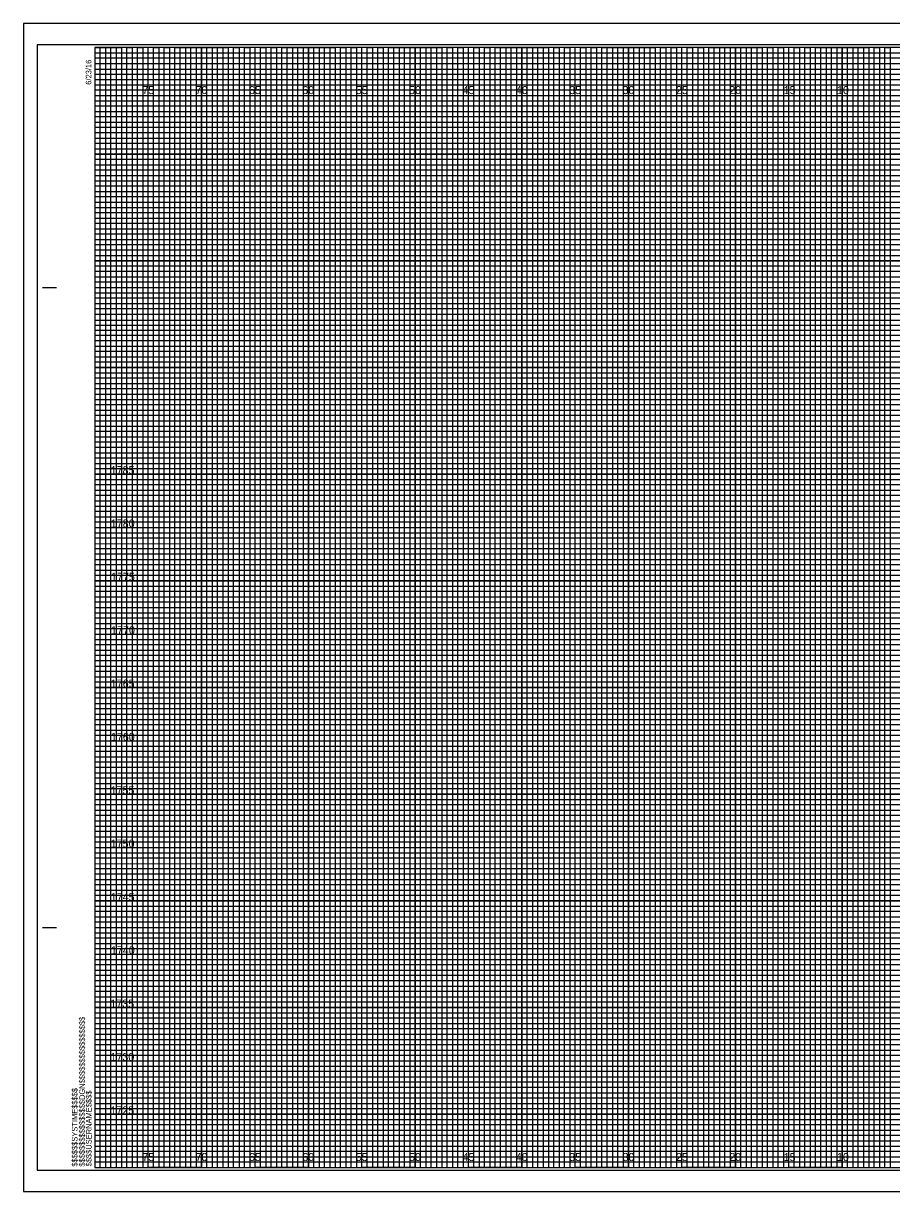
# Model space of a CAD drawing. Extents: x -7 to 162, y -2 to 437.
# Drawn here: x -6.7 to 74.6, y 107.7 to 217.2 of the extents above; entities that cross this region are included whole.
import ezdxf

# ---------------------------------------------------------------- set-up
doc = ezdxf.new("R2010")
doc.units = 0
for name, color, linetype in [('Raster_Level_0', 7, 'Continuous'), ('Scratch_Level_3', 7, 'Continuous'), ('Sheet Cross Section CELL', 7, 'Continuous'), ('Sheet Cross Section Grid Major CELL', 7, 'Continuous'), ('Sheet Cross Section Grid Middle CELL', 7, 'Continuous'), ('Sheet Cross Section Grid Minor 1 CELL', 7, 'Continuous'), ('Sheet Cross Section Grid Minor 2 CELL', 7, 'Continuous'), ('Sheet Cutting Line CELL', 7, 'Continuous'), ('Sheet DOT Grid CELL', 7, 'Continuous'), ('Sheet Plot Border Inside CELL', 7, 'Continuous'), ('Sheet Plot Border Outside CELL', 7, 'Continuous')]:
    doc.layers.add(name, color=color, linetype=linetype)

msp = doc.modelspace()

# ---------------------------------------------------------------- linework, layer by layer
at = {"layer": 'Sheet Cross Section CELL'}
for p, q in [((-4.9, 192.5), (-3.65, 192.5)), ((-4.85, 192.5), (-3.6, 192.5)), ((-4.9, 132.5), (-3.65, 132.5)), ((-4.85, 132.5), (-3.6, 132.5)), ((0, 110), (0, 110)), ((0, 110), (0, 110)), ((0, 110), (0, 110)), ((0, 110), (0, 110)), ((0, 110), (0, 110)), ((0, 110), (0, 110)), ((0, 110), (0, 110))]:
    msp.add_line(p, q, dxfattribs=at)
msp.add_lwpolyline([(160, 215), (0, 215), (0, 110), (160, 110)], close=True, dxfattribs=at)
at = {"layer": 'Sheet Cross Section Grid Major CELL'}
for p, q in [((5, 215), (0, 215)), ((5, 110), (5, 215)), ((15, 215), (10, 215)), ((10, 215), (10, 110)), ((15, 110), (15, 215)), ((25, 215), (20, 215)), ((20, 215), (20, 110)), ((25, 110), (25, 215)), ((35, 215), (30, 215)), ((30, 215), (30, 110)), ((35, 110), (35, 215)), ((45, 215), (40, 215)), ((40, 215), (40, 110)), ((45, 110), (45, 215)), ((55, 215), (50, 215)), ((50, 215), (50, 110)), ((55, 110), (55, 215)), ((65, 215), (60, 215)), ((60, 215), (60, 110)), ((65, 110), (65, 215)), ((75, 215), (70, 215)), ((70, 215), (70, 110)), ((10, 110), (5, 110)), ((20, 110), (15, 110)), ((30, 110), (25, 110)), ((40, 110), (35, 110)), ((50, 110), (45, 110)), ((60, 110), (55, 110)), ((70, 110), (65, 110))]:
    msp.add_line(p, q, dxfattribs=at)
for points in [[(0, 210), (160, 210), (160, 205), (0, 205)], [(0, 200), (160, 200), (160, 195), (0, 195)], [(0, 190), (160, 190), (160, 185), (0, 185)], [(0, 180), (160, 180), (160, 175), (0, 175)], [(0, 170), (160, 170), (160, 165), (0, 165)], [(0, 160), (160, 160), (160, 155), (0, 155)], [(0, 150), (160, 150), (160, 145), (0, 145)], [(0, 140), (160, 140), (160, 135), (0, 135)], [(0, 130), (160, 130), (160, 125), (0, 125)], [(0, 120), (160, 120), (160, 115), (0, 115)]]:
    msp.add_lwpolyline(points, dxfattribs=at)
at = {"layer": 'Sheet Cross Section Grid Middle CELL'}
for points in [[(0, 215), (2.5, 215), (2.5, 110), (7.5, 110), (7.5, 215), (12.5, 215), (12.5, 110), (17.5, 110), (17.5, 215), (22.5, 215), (22.5, 110), (27.5, 110), (27.5, 215), (32.5, 215), (32.5, 110), (37.5, 110), (37.5, 215), (42.5, 215), (42.5, 110), (47.5, 110), (47.5, 215), (52.5, 215), (52.5, 110), (57.5, 110), (57.5, 215), (62.5, 215), (62.5, 110), (67.5, 110), (67.5, 215), (72.5, 215), (72.5, 110), (77.5, 110)], [(0, 212.5), (137.5, 212.5)], [(0, 202.5), (160, 202.5), (160, 207.5), (0, 207.5)], [(0, 192.5), (160, 192.5), (160, 197.5), (0, 197.5)], [(0, 182.5), (160, 182.5), (160, 187.5), (0, 187.5)], [(0, 172.5), (160, 172.5), (160, 177.5), (0, 177.5)], [(0, 162.5), (160, 162.5), (160, 167.5), (0, 167.5)], [(0, 152.5), (160, 152.5), (160, 157.5), (0, 157.5)], [(0, 142.5), (160, 142.5), (160, 147.5), (0, 147.5)], [(0, 132.5), (160, 132.5), (160, 137.5), (0, 137.5)], [(0, 122.5), (160, 122.5), (160, 127.5), (0, 127.5)], [(0, 112.5), (160, 112.5), (160, 117.5), (0, 117.5)]]:
    msp.add_lwpolyline(points, dxfattribs=at)
at = {"layer": 'Sheet Cross Section Grid Minor 1 CELL'}
for p, q in [((0, 214.5), (130, 214.5)), ((130, 213.99), (0, 213.99)), ((0, 213.99), (0, 213.5)), ((0, 213.5), (130, 213.5)), ((130, 212.94), (0, 212.94)), ((0, 212.94), (0, 212)), ((0, 212), (160, 212))]:
    msp.add_line(p, q, dxfattribs=at)
for points in [[(0, 211.5), (135, 211.5), (160, 211.5), (160, 211), (0, 211)], [(0, 210.5), (160, 210.5), (160, 209.5), (0, 209.5)], [(0, 209), (160, 209), (160, 208.5), (0, 208.49)], [(0, 208), (160, 208), (160, 207), (0, 207)], [(0, 206.5), (160, 206.5), (160, 206), (0, 206)], [(0, 205.5), (160, 205.5), (160, 204.5), (0, 204.5)], [(0, 204), (160, 204), (160, 203.5), (0, 203.5)], [(0, 203), (160, 203), (160, 202), (0, 202)], [(0, 201.5), (160, 201.5), (160, 201), (0, 201)], [(0, 200.5), (160, 200.5), (160, 199.5), (0, 199.5)], [(0, 199), (160, 199), (160, 198.5), (0, 198.5)], [(0, 198), (160, 198), (160, 196.97), (160, 196.5), (160, 196), (0, 196)], [(0, 197), (160, 197), (160, 196.5), (0, 196.5)], [(0, 195.5), (160, 195.5), (160, 194.5), (0, 194.52)], [(0, 194.52), (160, 194.5), (160, 194), (0, 194)], [(0, 193.5), (160, 193.5), (160, 193), (0, 193)], [(0, 192), (160, 192), (160, 191.5), (0, 191.5)], [(0, 191), (160, 191), (160, 190.5), (0, 190.5)], [(-0.04, 189.44), (160, 189.44), (160, 188.94), (-0.04, 188.94)], [(0, 188.5), (160, 188.5), (160, 188), (0, 188)], [(0, 187), (160, 187), (160, 186.5), (0, 186.5)], [(0, 186), (160, 186), (160, 185.5), (0, 185.5)], [(0, 184.5), (160, 184.5), (160, 184), (0, 184)], [(0, 183.5), (160, 183.5), (160, 183), (0, 183)], [(0, 182), (160, 182), (160, 181.5), (0, 181.5)], [(0, 181), (160, 181), (160, 180.5), (0, 180.5)], [(0, 179.5), (160, 179.5), (160, 178.99), (0, 179)], [(0, 178.5), (160, 178.5), (160, 178), (0, 178)], [(0, 177), (160, 177), (160, 176.5), (0, 176.5)], [(0, 176), (160, 176), (160, 175.5), (0, 175.5)], [(0, 174.5), (160, 174.5), (160, 174), (0, 174)], [(0, 173.5), (160, 173.5), (160, 173), (0, 173)], [(0, 172), (160, 172), (160, 171.5), (0, 171.5)], [(0, 171), (160, 171), (160, 170.5), (0, 170.5)], [(0, 169.5), (160, 169.5), (160, 169), (0, 169)], [(0, 168.5), (160.03, 168.46), (160, 168), (0, 168)], [(0, 167), (160, 167), (160, 166.5), (0, 166.5)], [(0, 166), (160, 166), (160, 165.5), (0, 165.5)], [(0, 164.5), (160, 164.5), (160, 164), (0, 164)], [(0, 163.5), (160, 163.5), (160, 163), (0, 163)], [(0, 162), (160, 162), (160, 161.5), (0, 161.5)], [(0, 161), (160, 161), (160, 160.5), (0, 160.5)], [(0, 159.5), (160, 159.5), (160, 159), (0, 159)], [(0, 158.5), (160, 158.5), (160, 158), (0, 158)], [(0, 157), (160, 157), (160, 156.5), (0, 156.5)], [(0, 156), (160, 156), (160, 155.5), (0, 155.5)], [(0, 154.5), (160, 154.5), (160, 154), (0, 154)], [(0, 153.5), (160, 153.5), (160, 153), (0, 153)], [(0, 152), (160, 152), (160, 151.5), (0, 151.5)], [(0, 151), (160, 151), (160, 150.5), (0, 150.5)], [(0, 149.5), (160, 149.5), (160, 148.99), (0, 149)], [(0, 148.5), (160, 148.5), (160, 148), (0, 148)], [(0, 147), (160, 147), (160, 146.5), (0, 146.5)], [(0, 146), (160, 146), (160, 145.5), (0, 145.5)], [(0, 144.5), (160, 144.5), (160, 144), (0, 144)], [(0, 143.5), (160, 143.5), (160, 143), (0, 143)], [(0, 142), (160, 142), (160, 141.5), (0, 141.5)], [(0, 141), (160, 141), (160, 140.5), (0, 140.5)], [(0, 139.5), (160, 139.5), (160, 139), (0, 139)], [(0, 138.5), (160.03, 138.46), (160, 138), (0, 138)], [(0, 137), (160, 137), (160, 136.5), (0, 136.5)], [(0, 136), (160, 136), (160, 135.5), (0, 135.5)], [(0, 134.5), (160, 134.5), (160, 134), (0, 134)], [(0, 133.5), (160, 133.5), (160, 133), (0, 133)], [(0, 132), (160, 132), (160, 131.5), (0, 131.5)], [(0, 131), (160, 131), (160, 130.5), (0, 130.5)], [(0, 129.5), (160, 129.5), (160, 129), (0, 129)], [(0, 128.5), (160, 128.5), (160, 128), (0, 128)], [(0, 127), (160, 127), (160, 126.5), (0, 126.5)], [(0, 126), (160, 126), (160, 125.5), (0, 125.5)], [(0, 124.5), (160, 124.5), (160, 124), (0, 124)], [(0, 123.5), (160, 123.5), (160, 123), (0, 123)], [(0, 122), (160, 122), (160, 121.5), (0, 121.5)], [(0, 121), (160, 121), (160, 120.5), (0, 120.5)], [(0, 119.5), (160, 119.5), (160, 119), (0, 119)], [(0, 118.5), (160, 118.5), (160, 118), (0, 118)], [(0, 117), (160, 117), (160, 116.5), (0, 116.5)], [(0, 116), (160, 116), (160, 115.5), (0, 115.5)], [(0, 114.5), (160, 114.5), (160, 114), (0, 114)], [(0, 113.5), (160, 113.5), (160, 113), (0, 113)], [(0, 112), (160, 112), (160, 111.5), (0, 111.5)], [(0, 111), (160, 111), (160, 110.5), (0, 110.5)]]:
    msp.add_lwpolyline(points, dxfattribs=at)
at = {"layer": 'Sheet Cross Section Grid Minor 2 CELL'}
for points in [[(0, 110), (0.5, 110), (0.5, 215), (1, 215), (1, 110)], [(1, 110), (1.5, 110), (1.5, 215), (2, 215), (2, 110)], [(2.5, 110), (3, 110), (3, 215), (3.5, 215), (3.5, 110)], [(3.5, 110), (4, 110), (4, 215), (4.5, 215), (4.5, 110)], [(5, 110), (5.5, 110), (5.5, 215), (6, 215), (6, 110)], [(6, 110), (6.5, 110), (6.5, 215), (7, 215), (7, 110)], [(7.5, 110), (8, 110), (8, 215), (8.5, 215), (8.5, 110)], [(8.5, 110), (9, 110), (9, 215), (9.5, 215), (9.5, 110)], [(10, 110), (10.5, 110), (10.5, 215), (11, 215), (11, 110)], [(11, 110), (11.5, 110), (11.5, 215), (12, 215), (12, 110)], [(12.5, 110), (13, 110), (13, 215), (13.5, 215), (13.5, 110)], [(13.5, 110), (14, 110), (14, 215), (14.5, 215), (14.5, 110)], [(15, 110), (15.5, 110), (15.5, 215), (16, 215), (16, 110)], [(16, 110), (16.5, 110), (16.5, 215), (17, 215), (17, 110)], [(17.5, 110), (18, 110), (18, 215), (18.5, 215), (18.5, 110)], [(18.5, 110), (19, 110), (19, 215), (19.5, 215), (19.5, 110)], [(20, 110), (20.5, 110), (20.5, 215), (21, 215), (21, 110)], [(21, 110), (21.5, 110), (21.5, 215), (22, 215), (22, 110)], [(22.5, 110), (23, 110), (23, 215), (23.5, 215), (23.5, 110)], [(23.5, 110), (24, 110), (24, 215), (24.5, 215), (24.5, 110)], [(25, 110), (25.5, 110), (25.5, 215), (26, 215), (26, 110)], [(26, 110), (26.5, 110), (26.5, 215), (27, 215), (27, 110)], [(27.5, 110), (28, 110), (28, 215), (28.5, 215), (28.5, 110)], [(28.5, 110), (29, 110), (29, 215), (29.5, 215), (29.5, 110)], [(30, 110), (30.5, 110), (30.5, 215), (31, 215), (31, 110)], [(31, 110), (31.5, 110), (31.5, 215), (32, 215), (32, 110)], [(32.5, 110), (33, 110), (33, 215), (33.5, 215), (33.5, 110)], [(33.5, 110), (34, 110), (34, 215), (34.5, 215), (34.5, 110)], [(35, 110), (35.5, 110), (35.5, 215), (36, 215), (36, 110)], [(36, 110), (36.5, 110), (36.5, 215), (37, 215), (37, 110)], [(37.5, 110), (38, 110), (38, 215), (38.5, 215), (38.5, 110)], [(38.5, 110), (39, 110), (39, 215), (39.5, 215), (39.5, 110)], [(40, 110), (40.5, 110), (40.5, 215), (41, 215), (41, 110)], [(41, 110), (41.5, 110), (41.5, 215), (42, 215), (42, 110)], [(42.5, 110), (43, 110), (43, 215), (43.5, 215), (43.5, 110)], [(43.5, 110), (44, 110), (44, 215), (44.5, 215), (44.5, 110)], [(45, 110), (45.5, 110), (45.5, 215), (46, 215), (46, 110)], [(46, 110), (46.5, 110), (46.5, 215), (47, 215), (47, 110)], [(47.5, 110), (48, 110), (48, 215), (48.5, 215), (48.5, 110)], [(48.5, 110), (49, 110), (49, 215), (49.5, 215), (49.5, 110)], [(50, 110), (50.5, 110), (50.5, 215), (51, 215), (51, 110)], [(51, 110), (51.5, 110), (51.5, 215), (52, 215), (52, 110)], [(52.5, 110), (53, 110), (53, 215), (53.5, 215), (53.5, 110)], [(53.5, 110), (54, 110), (54, 215), (54.5, 215), (54.5, 110)], [(55, 110), (55.5, 110), (55.5, 215), (56, 215), (56, 110)], [(56, 110), (56.5, 110), (56.5, 215), (57, 215), (57, 110)], [(57.5, 110), (58, 110), (58, 215), (58.5, 215), (58.5, 110)], [(58.5, 110), (59, 110), (59, 215), (59.5, 215), (59.5, 110)], [(60, 110), (60.5, 110), (60.5, 215), (61, 215), (61, 110)], [(61, 110), (61.5, 110), (61.5, 215), (62, 215), (62, 110)], [(62.5, 110), (63, 110), (63, 215), (63.5, 215), (63.5, 110)], [(63.5, 110), (64, 110), (64, 215), (64.5, 215), (64.5, 110)], [(65, 110), (65.5, 110), (65.5, 215), (66, 215), (66, 110)], [(66, 110), (66.5, 110), (66.5, 215), (67, 215), (67, 110)], [(67.5, 110), (68, 110), (68, 215), (68.5, 215), (68.5, 110)], [(68.5, 110), (69, 110), (69, 215), (69.5, 215), (69.5, 110)], [(70, 110), (70.5, 110), (70.5, 215), (71, 215), (71, 110)], [(71, 110), (71.5, 110), (71.5, 215), (72, 215), (72, 110)], [(72.5, 110), (73, 110), (73, 215), (73.5, 215), (73.5, 110)], [(73.5, 110), (74, 110), (74, 215), (74.5, 215), (74.5, 110)]]:
    msp.add_lwpolyline(points, dxfattribs=at)
at = {"layer": 'Sheet Cutting Line CELL'}
for p, q in [((161.65, 217.25), (-6.7, 217.25)), ((-6.7, 217.25), (-6.7, 107.75)), ((-6.7, 107.75), (161.65, 107.75))]:
    msp.add_line(p, q, dxfattribs=at)
at = {"layer": 'Sheet DOT Grid CELL'}
for p, q in [((5, 110), (5, 215)), ((10, 110), (10, 215)), ((15, 110), (15, 215)), ((20, 110), (20, 215)), ((25, 110), (25, 215)), ((30, 110), (30, 215)), ((35, 110), (35, 215)), ((40, 110), (40, 215)), ((45, 110), (45, 215)), ((50, 110), (50, 215)), ((55, 110), (55, 215)), ((60, 110), (60, 215)), ((65, 110), (65, 215)), ((70, 110), (70, 215)), ((0, 210), (160, 210)), ((0, 205), (160, 205)), ((0, 200), (160, 200)), ((0, 195), (160, 195)), ((0, 190), (160, 190)), ((0, 185), (160, 185)), ((0, 180), (160, 180)), ((0, 175), (160, 175)), ((0, 170), (160, 170)), ((0, 165), (160, 165)), ((0, 160), (160, 160)), ((0, 155), (160, 155)), ((0, 150), (160, 150)), ((0, 145), (160, 145)), ((0, 140), (160, 140)), ((0, 135), (160, 135)), ((0, 130), (160, 130)), ((0, 125), (160, 125)), ((0, 120), (160, 120)), ((0, 115), (160, 115))]:
    msp.add_line(p, q, dxfattribs=at)
at = {"layer": 'Sheet Plot Border Inside CELL'}
msp.add_lwpolyline([(-5.4, 109.75), (161.2, 109.75), (161.2, 215.25), (-5.4, 215.25)], close=True, dxfattribs=at)
at = {"layer": 'Sheet Plot Border Outside CELL'}
msp.add_lwpolyline([(-6.7, 107.75), (161.65, 107.75), (161.65, 217.25), (-6.7, 217.25)], close=True, dxfattribs=at)

# ---------------------------------------------------------------- texts
at = {"layer": 'Raster_Level_0'}
for s, p in [('75', (4.44, 210.62)), ('70', (9.43, 210.62)), ('65', (14.44, 210.62)), ('60', (19.43, 210.62)), ('55', (24.44, 210.62)), ('50', (29.43, 210.62)), ('45', (34.44, 210.62)), ('40', (39.43, 210.62)), ('35', (44.44, 210.62)), ('30', (49.43, 210.62)), ('25', (54.44, 210.62)), ('20', (59.43, 210.62)), ('15', (64.53, 210.62)), ('10', (69.52, 210.62)), ('75', (4.44, 110.62)), ('70', (9.43, 110.62)), ('65', (14.44, 110.62)), ('60', (19.43, 110.62)), ('55', (24.44, 110.62)), ('50', (29.43, 110.62)), ('45', (34.44, 110.62)), ('40', (39.43, 110.62)), ('35', (44.44, 110.62)), ('30', (49.43, 110.62)), ('25', (54.44, 110.62)), ('20', (59.43, 110.62)), ('15', (64.53, 110.62)), ('10', (69.52, 110.62))]:
    msp.add_text(s, height=0.75, dxfattribs=at).set_placement(p)
at = {"layer": 'Scratch_Level_3'}
for s, p in [('1785', (1.48, 175)), ('1780', (1.49, 170)), ('1775', (1.51, 165)), ('1770', (1.52, 160)), ('1765', (1.49, 155)), ('1760', (1.5, 150)), ('1755', (1.47, 145)), ('1750', (1.48, 140)), ('1745', (1.49, 135)), ('1740', (1.5, 130)), ('1735', (1.45, 125)), ('1730', (1.46, 120)), ('1725', (1.46, 115))]:
    msp.add_text(s, height=0.75, dxfattribs=at).set_placement(p)
at = {"layer": 'Sheet Cross Section CELL'}
for s, p in [('6/23/16', (-0.33, 211.5)), ('$$$$$$$$$$$$$$$$DGN$$$$$$$$$$$$$$$$', (-0.94, 110.09)), ('$$$$$$SYSTIME$$$$$', (-1.63, 110.09)), ('$$$$USERNAME$$$$', (-0.31, 110.12))]:
    msp.add_text(s, height=0.525, rotation=90, dxfattribs=at).set_placement(p)

doc.saveas('drawing.dxf')
